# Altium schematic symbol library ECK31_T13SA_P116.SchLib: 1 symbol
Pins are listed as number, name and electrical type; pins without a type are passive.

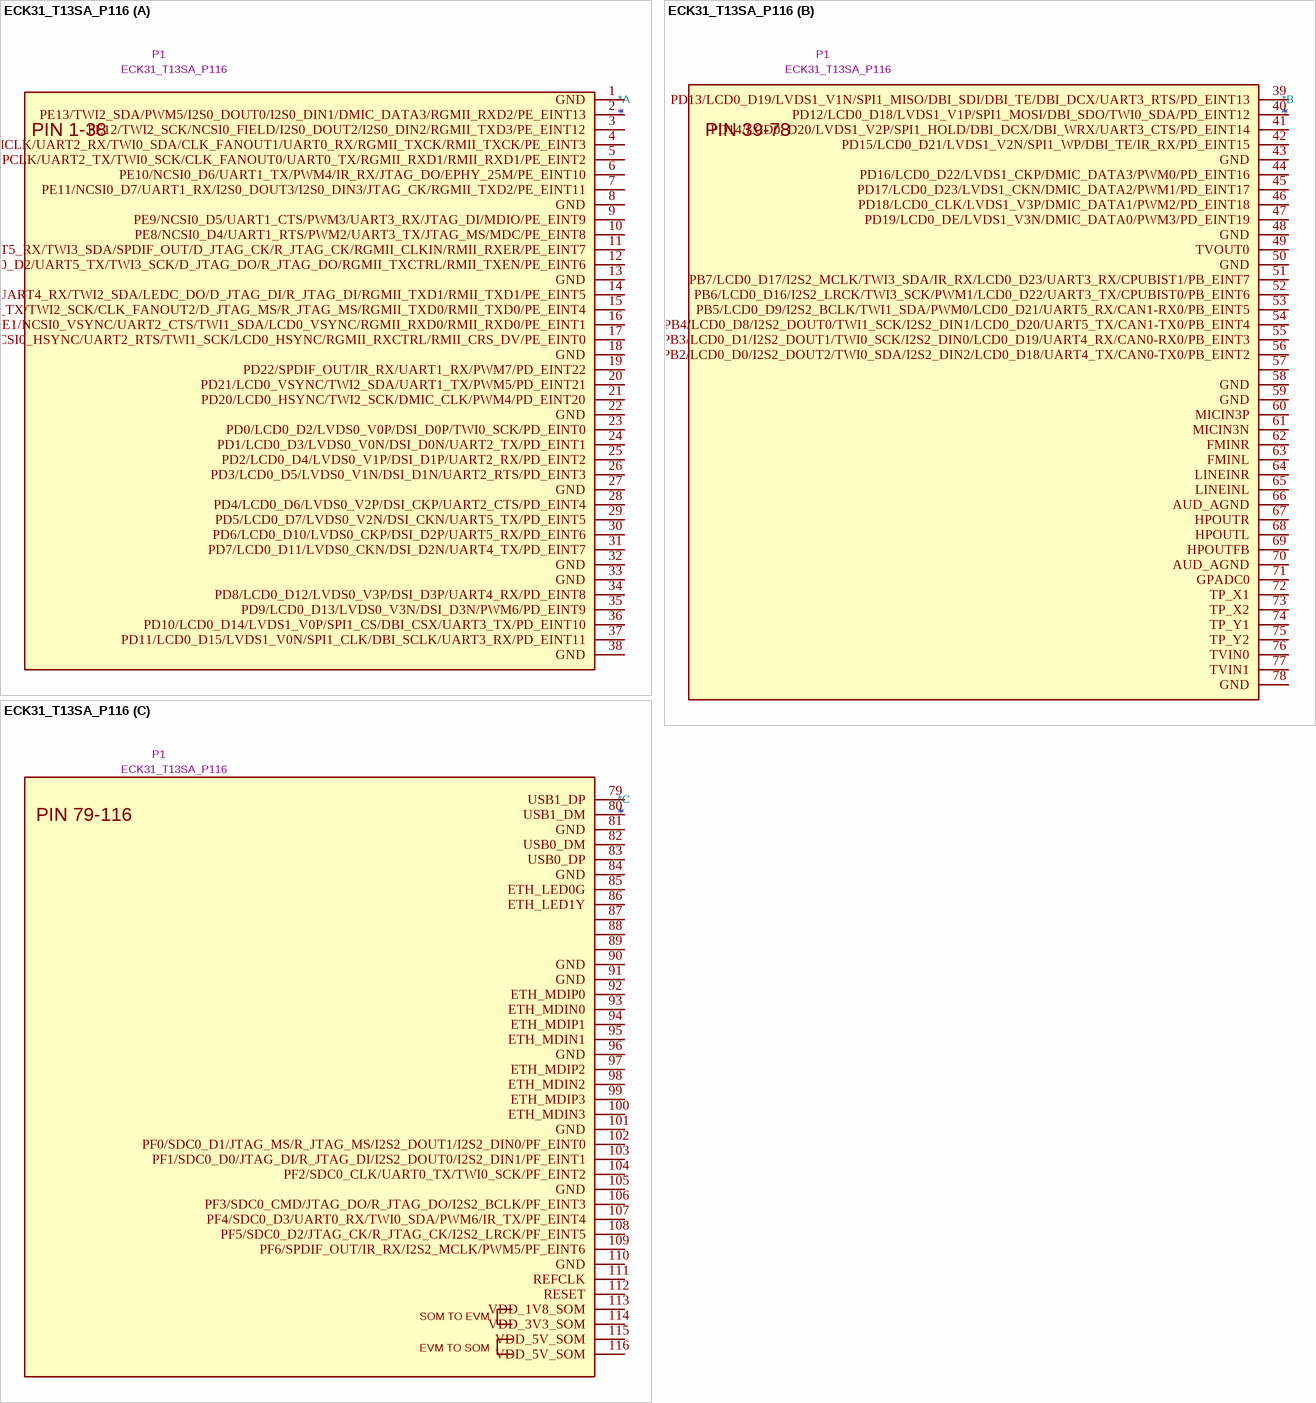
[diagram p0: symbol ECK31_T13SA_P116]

## ECK31_T13SA_P116
designator *  value ECK31_T13SA_P116  Reference: P1
part A pins: 1 GND, 2 PE13/TWI2_SDA/PWM5/I2S0_DOUT0/I2S0_DIN1/DMIC_DATA3/RGMII_RXD2/PE_EINT13, 3 PE12/TWI2_SCK/NCSI0_FIELD/I2S0_DOUT2/I2S0_DIN2/RGMII_TXD3/PE_EINT12, 4 PE3/NCSI0_MCLK/UART2_RX/TWI0_SDA/CLK_FANOUT1/UART0_RX/RGMII_TXCK/RMII_TXCK/PE_EINT3, 5 PE2/NCSI0_PCLK/UART2_TX/TWI0_SCK/CLK_FANOUT0/UART0_TX/RGMII_RXD1/RMII_RXD1/PE_EINT2, 6 PE10/NCSI0_D6/UART1_TX/PWM4/IR_RX/JTAG_DO/EPHY_25M/PE_EINT10, 7 PE11/NCSI0_D7/UART1_RX/I2S0_DOUT3/I2S0_DIN3/JTAG_CK/RGMII_TXD2/PE_EINT11, 8 GND, 9 PE9/NCSI0_D5/UART1_CTS/PWM3/UART3_RX/JTAG_DI/MDIO/PE_EINT9, 10 PE8/NCSI0_D4/UART1_RTS/PWM2/UART3_TX/JTAG_MS/MDC/PE_EINT8, 11 PE7/NCSI0_D3/UART5_RX/TWI3_SDA/SPDIF_OUT/D_JTAG_CK/R_JTAG_CK/RGMII_CLKIN/RMII_RXER/PE_EINT7, 12 PE6/NCSI0_D2/UART5_TX/TWI3_SCK/D_JTAG_DO/R_JTAG_DO/RGMII_TXCTRL/RMII_TXEN/PE_EINT6, 13 GND, 14 PE5/NCSI0_D1/UART4_RX/TWI2_SDA/LEDC_DO/D_JTAG_DI/R_JTAG_DI/RGMII_TXD1/RMII_TXD1/PE_EINT5, 15 PE4/NCSI0_D0/UART4_TX/TWI2_SCK/CLK_FANOUT2/D_JTAG_MS/R_JTAG_MS/RGMII_TXD0/RMII_TXD0/PE_EINT4, 16 PE1/NCSI0_VSYNC/UART2_CTS/TWI1_SDA/LCD0_VSYNC/RGMII_RXD0/RMII_RXD0/PE_EINT1, 17 PE0/NCSI0_HSYNC/UART2_RTS/TWI1_SCK/LCD0_HSYNC/RGMII_RXCTRL/RMII_CRS_DV/PE_EINT0, 18 GND, 19 PD22/SPDIF_OUT/IR_RX/UART1_RX/PWM7/PD_EINT22, 20 PD21/LCD0_VSYNC/TWI2_SDA/UART1_TX/PWM5/PD_EINT21, 21 PD20/LCD0_HSYNC/TWI2_SCK/DMIC_CLK/PWM4/PD_EINT20, 22 GND, 23 PD0/LCD0_D2/LVDS0_V0P/DSI_D0P/TWI0_SCK/PD_EINT0, 24 PD1/LCD0_D3/LVDS0_V0N/DSI_D0N/UART2_TX/PD_EINT1, 25 PD2/LCD0_D4/LVDS0_V1P/DSI_D1P/UART2_RX/PD_EINT2, 26 PD3/LCD0_D5/LVDS0_V1N/DSI_D1N/UART2_RTS/PD_EINT3, 27 GND, 28 PD4/LCD0_D6/LVDS0_V2P/DSI_CKP/UART2_CTS/PD_EINT4, 29 PD5/LCD0_D7/LVDS0_V2N/DSI_CKN/UART5_TX/PD_EINT5, 30 PD6/LCD0_D10/LVDS0_CKP/DSI_D2P/UART5_RX/PD_EINT6, 31 PD7/LCD0_D11/LVDS0_CKN/DSI_D2N/UART4_TX/PD_EINT7, 32 GND, 33 GND, 34 PD8/LCD0_D12/LVDS0_V3P/DSI_D3P/UART4_RX/PD_EINT8, 35 PD9/LCD0_D13/LVDS0_V3N/DSI_D3N/PWM6/PD_EINT9, 36 PD10/LCD0_D14/LVDS1_V0P/SPI1_CS/DBI_CSX/UART3_TX/PD_EINT10, 37 PD11/LCD0_D15/LVDS1_V0N/SPI1_CLK/DBI_SCLK/UART3_RX/PD_EINT11, 38 GND
part B pins: 39 PD13/LCD0_D19/LVDS1_V1N/SPI1_MISO/DBI_SDI/DBI_TE/DBI_DCX/UART3_RTS/PD_EINT13, 40 PD12/LCD0_D18/LVDS1_V1P/SPI1_MOSI/DBI_SDO/TWI0_SDA/PD_EINT12, 41 PD14/LCD0_D20/LVDS1_V2P/SPI1_HOLD/DBI_DCX/DBI_WRX/UART3_CTS/PD_EINT14, 42 PD15/LCD0_D21/LVDS1_V2N/SPI1_WP/DBI_TE/IR_RX/PD_EINT15, 43 GND, 44 PD16/LCD0_D22/LVDS1_CKP/DMIC_DATA3/PWM0/PD_EINT16, 45 PD17/LCD0_D23/LVDS1_CKN/DMIC_DATA2/PWM1/PD_EINT17, 46 PD18/LCD0_CLK/LVDS1_V3P/DMIC_DATA1/PWM2/PD_EINT18, 47 PD19/LCD0_DE/LVDS1_V3N/DMIC_DATA0/PWM3/PD_EINT19, 48 GND, 49 TVOUT0, 50 GND, 51 PB7/LCD0_D17/I2S2_MCLK/TWI3_SDA/IR_RX/LCD0_D23/UART3_RX/CPUBIST1/PB_EINT7, 52 PB6/LCD0_D16/I2S2_LRCK/TWI3_SCK/PWM1/LCD0_D22/UART3_TX/CPUBIST0/PB_EINT6, 53 PB5/LCD0_D9/I2S2_BCLK/TWI1_SDA/PWM0/LCD0_D21/UART5_RX/CAN1-RX0/PB_EINT5, 54 PB4/LCD0_D8/I2S2_DOUT0/TWI1_SCK/I2S2_DIN1/LCD0_D20/UART5_TX/CAN1-TX0/PB_EINT4, 55 PB3/LCD0_D1/I2S2_DOUT1/TWI0_SCK/I2S2_DIN0/LCD0_D19/UART4_RX/CAN0-RX0/PB_EINT3, 56 PB2/LCD0_D0/I2S2_DOUT2/TWI0_SDA/I2S2_DIN2/LCD0_D18/UART4_TX/CAN0-TX0/PB_EINT2, 57, 58 GND, 59 GND, 60 MICIN3P, 61 MICIN3N, 62 FMINR, 63 FMINL, 64 LINEINR, 65 LINEINL, 66 AUD_AGND, 67 HPOUTR, 68 HPOUTL, 69 HPOUTFB, 70 AUD_AGND, 71 GPADC0, 72 TP_X1, 73 TP_X2, 74 TP_Y1, 75 TP_Y2, 76 TVIN0, 77 TVIN1, 78 GND
part C pins: 79 USB1_DP, 80 USB1_DM, 81 GND, 82 USB0_DM, 83 USB0_DP, 84 GND, 85 ETH_LED0G, 86 ETH_LED1Y, 87, 88, 89, 90 GND, 91 GND, 92 ETH_MDIP0, 93 ETH_MDIN0, 94 ETH_MDIP1, 95 ETH_MDIN1, 96 GND, 97 ETH_MDIP2, 98 ETH_MDIN2, 99 ETH_MDIP3, 100 ETH_MDIN3, 101 GND, 102 PF0/SDC0_D1/JTAG_MS/R_JTAG_MS/I2S2_DOUT1/I2S2_DIN0/PF_EINT0, 103 PF1/SDC0_D0/JTAG_DI/R_JTAG_DI/I2S2_DOUT0/I2S2_DIN1/PF_EINT1, 104 PF2/SDC0_CLK/UART0_TX/TWI0_SCK/PF_EINT2, 105 GND, 106 PF3/SDC0_CMD/JTAG_DO/R_JTAG_DO/I2S2_BCLK/PF_EINT3, 107 PF4/SDC0_D3/UART0_RX/TWI0_SDA/PWM6/IR_TX/PF_EINT4, 108 PF5/SDC0_D2/JTAG_CK/R_JTAG_CK/I2S2_LRCK/PF_EINT5, 109 PF6/SPDIF_OUT/IR_RX/I2S2_MCLK/PWM5/PF_EINT6, 110 GND, 111 REFCLK, 112 RESET, 113 VDD_1V8_SOM, 114 VDD_3V3_SOM, 115 VDD_5V_SOM, 116 VDD_5V_SOM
